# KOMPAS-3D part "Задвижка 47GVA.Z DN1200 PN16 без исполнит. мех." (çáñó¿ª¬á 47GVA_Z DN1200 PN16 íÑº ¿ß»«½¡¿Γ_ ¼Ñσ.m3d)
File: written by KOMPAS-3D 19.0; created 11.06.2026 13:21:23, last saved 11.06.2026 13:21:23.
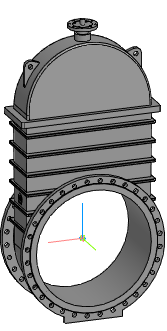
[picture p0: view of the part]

Document properties: Автор: Евгений; Полное имя файла: Z:\3.Личные\kachalov\001_3d для проектировщиков\2.2 Тип 47GVA, 47GVA.Z\_stp\_stp_Задвижка 47GVA.Z DN350-DN1200 без исп.мех\Задвижка 47GVA_Z DN1200 PN16 без исполнит_ мех.m3d

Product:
- Part/product: Задвижка 47GVA.Z DN1200 PN16 без исполнит. мех.

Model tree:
1. Операция без истории:1  (labels: Задвижка 47GVA.Z DN1200 PN16 без исполнит. мех.)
